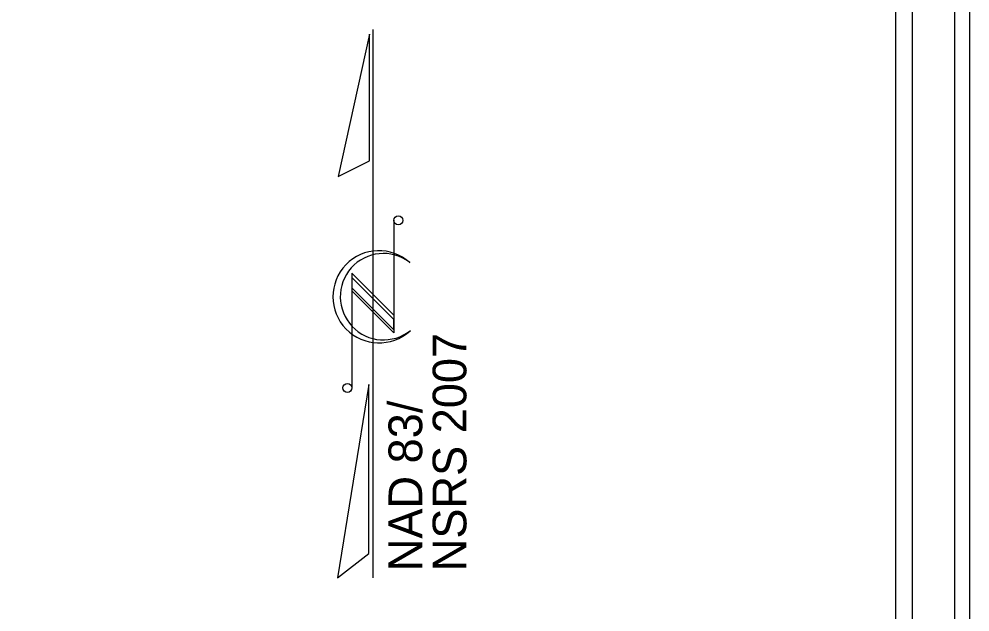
# Model space of a CAD drawing. Extents: x 1530800 to 1534168, y 642962 to 645162.
# Drawn here: x 1533604 to 1534168, y 644102 to 644454 of the extents above; entities that cross this region are included whole.
import ezdxf

# ---------------------------------------------------------------- set-up
doc = ezdxf.new("R2010")
doc.units = 0
for name, color, linetype in [('Prop Shade Light', 7, 'Continuous'), ('Sheet North Arrow CELL', 7, 'Continuous'), ('Sheet Plot Border Inside CELL', 7, 'Continuous'), ('Sheet Plot Border Outside CELL', 7, 'Continuous'), ('Sheet Title CELL', 7, 'Continuous')]:
    doc.layers.add(name, color=color, linetype=linetype)

# ---------------------------------------------------------------- blocks, each defined once
blk = doc.blocks.new('NORTH ARROW NAD83 NSRS 2007')
at = {"layer": 'Sheet North Arrow CELL'}
for p, q in [((0, -3.25), (0, 3.25)), ((0.245, 0.988), (0.245, -0.346)), ((0.429, 0.491), (0.436, 0.486)), ((0.245, -0.138), (-0.252, 0.359)), ((-0.252, 0.359), (-0.252, -0.997)), ((0.245, -0.187), (-0.252, 0.31)), ((-0.252, 0.31), (-0.252, 0.188)), ((0.245, -0.309), (-0.252, 0.188)), ((-0.252, 0.188), (0.245, -0.309)), ((0.245, -0.346), (-0.252, 0.151)), ((0.245, -0.309), (0.245, -0.187))]:
    blk.add_line(p, q, dxfattribs=at)
for points in [[(-0.045, 3.193), (-0.416, 1.505), (-0.045, 1.693)], [(-0.053, -0.96), (-0.421, -3.25), (-0.053, -2.96)]]:
    blk.add_lwpolyline(points, close=True, dxfattribs=at)
for centre in [(0.298, 0.987), (-0.305, -0.999)]:
    blk.add_circle(centre, 0.053, dxfattribs=at)
for centre, radius, start, end in [((0.069, 0.081), 0.546, 47.84, 312.3941), ((0.122, 0.082), 0.512, 53.095, 308.6287)]:
    blk.add_arc(centre, radius, start, end, dxfattribs=at)
for s, p in [('NSRS 2007', (1.106, -3.172)), ('NAD 83/', (0.582, -3.172))]:
    blk.add_text(s, height=0.4, rotation=90, dxfattribs=at).set_placement(p)

msp = doc.modelspace()

# ---------------------------------------------------------------- linework, layer by layer
at = {"layer": 'Sheet Plot Border Inside CELL'}
msp.add_lwpolyline([(1530826.37, 643007.18), (1534159.37, 643007.18), (1534159.37, 645117.38), (1530826.37, 645117.38)], close=True, dxfattribs=at)
at = {"layer": 'Sheet Plot Border Outside CELL'}
msp.add_line((1534168.37, 642962.3), (1534168.37, 645162.28), dxfattribs=at)
at = {"layer": 'Sheet Title CELL'}
for points in [[(1534134.37, 643032.3), (1534134.37, 645092.28)], [(1534124.37, 643412.28), (1534124.37, 645082.3)]]:
    msp.add_lwpolyline(points, dxfattribs=at)

# ---------------------------------------------------------------- block references
at = {"layer": 'Prop Shade Light', "xscale": 50, "yscale": 50.00000000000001, "rotation": -0.0001328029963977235}
msp.add_blockref('NORTH ARROW NAD83 NSRS 2007', (1533814.4, 644284.9), dxfattribs=at)

doc.saveas('drawing.dxf')
